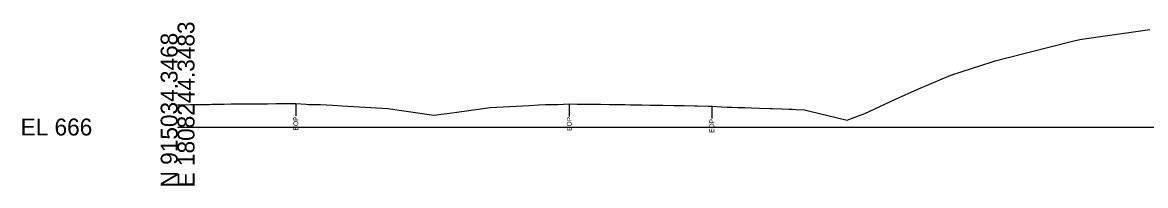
# Model space of a CAD drawing. Extents: x -26 to 403, y -10 to 8517.
# Drawn here: x -25.7 to 160.3, y 2990.3 to 3017.3 of the extents above; entities that cross this region are included whole.
import ezdxf

# ---------------------------------------------------------------- set-up
doc = ezdxf.new("R2010")
doc.units = 0
for name, color, linetype in [('Exist Cross Section Cell', 7, 'Continuous'), ('Exist XS Ground Line', 7, 'Continuous'), ('Old_Level_10', 7, 'Continuous')]:
    doc.layers.add(name, color=color, linetype=linetype)

msp = doc.modelspace()

# ---------------------------------------------------------------- linework, layer by layer
at = {"layer": 'Exist Cross Section Cell'}
msp.add_line((0, 3000), (200, 3000), dxfattribs=at)
at = {"layer": 'Exist XS Ground Line'}
msp.add_lwpolyline([(0, 3003.67), (0.32, 3003.68), (2.16, 3003.71), (5.29, 3003.75), (5.65, 3003.76), (6.1, 3003.77), (7.74, 3003.79), (8.86, 3003.83), (10.08, 3003.84), (11.69, 3003.85), (14.08, 3003.86), (14.54, 3003.86), (14.9, 3003.86), (16.34, 3003.87), (18.15, 3003.88), (19.58, 3003.89), (21.31, 3003.77), (21.66, 3003.74), (22.09, 3003.75), (22.64, 3003.75), (23.68, 3003.75), (25.65, 3003.64), (27.25, 3003.53), (34.81, 3003.06), (37.87, 3002.63), (42.46, 3001.95), (45.86, 3002.42), (51.75, 3003.23), (58.29, 3003.59), (59.79, 3003.67), (60.93, 3003.73), (62.12, 3003.72), (62.96, 3003.73), (64.86, 3003.82), (66.2, 3003.79), (66.78, 3003.79), (69.68, 3003.76), (70.06, 3003.76), (71.45, 3003.75), (72.54, 3003.73), (74.06, 3003.71), (75, 3003.7), (75.77, 3003.68), (76.88, 3003.65), (78.25, 3003.64), (78.55, 3003.63), (78.95, 3003.63), (80.35, 3003.6), (82.15, 3003.58), (83.91, 3003.55), (85.67, 3003.51), (86.05, 3003.51), (87.89, 3003.48), (88.48, 3003.47), (90.07, 3003.35), (91.02, 3003.3), (91.79, 3003.28), (92.8, 3003.25), (94.02, 3003.21), (95.01, 3003.19), (96.36, 3003.14), (98.14, 3003.07), (98.45, 3003.07), (100.07, 3003), (101.29, 3002.95), (101.78, 3002.93), (102.47, 3002.9), (103.81, 3002.82), (104.72, 3002.61), (110.88, 3001.16), (111.72, 3001.48), (113.83, 3002.22), (118.91, 3004.59), (122.57, 3006.27), (128.05, 3008.61), (134.9, 3010.81), (135.38, 3010.95), (137.33, 3011.44), (148.2, 3014.24), (149.4, 3014.52), (150.89, 3014.73), (161.01, 3016.13)], dxfattribs=at)
at = {"layer": 'Old_Level_10'}
for p, q in [((19.58, 3003.89), (19.58, 3001.84)), ((64.86, 3003.82), (64.86, 3001.77)), ((88.48, 3003.47), (88.48, 3001.42))]:
    msp.add_line(p, q, dxfattribs=at)

# ---------------------------------------------------------------- texts
at = {"layer": 'Exist Cross Section Cell'}
for s, p in [('E 1808244.3483', (2.8, 2990)), ('N 915034.3468', (0, 2990))]:
    msp.add_text(s, height=2.8, rotation=90, dxfattribs=at).set_placement(p)
msp.add_text('EL 666', height=2.8, dxfattribs=at).set_placement((-26, 2998.6))
at = {"layer": 'Old_Level_10'}
for p in [(19.97, 2999.44), (65.26, 2999.37), (88.87, 2999.02)]:
    msp.add_text('EOP', height=0.787, rotation=90, dxfattribs=at).set_placement(p)

doc.saveas('drawing.dxf')
